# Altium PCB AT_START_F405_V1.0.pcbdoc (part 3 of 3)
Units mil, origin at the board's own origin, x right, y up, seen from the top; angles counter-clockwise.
Board outline 15424.54 x 3535.36 mil, 2 copper layers (Top Layer, Bottom Layer); 147 components, 139 nets, 556 pads, 794 vias.
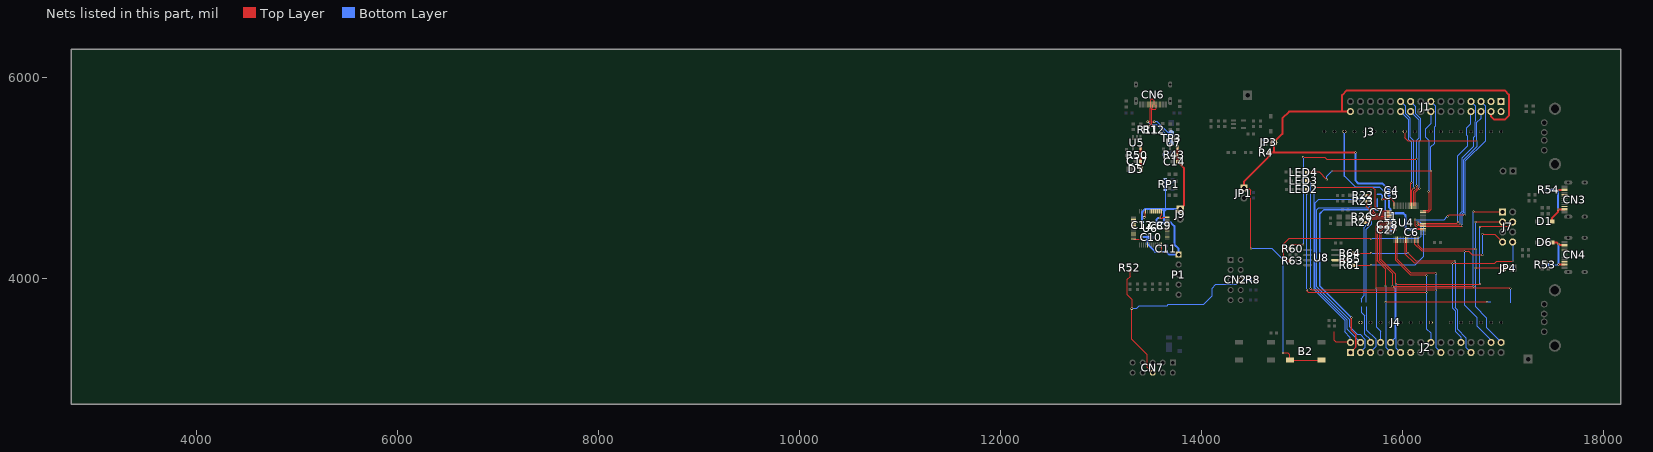
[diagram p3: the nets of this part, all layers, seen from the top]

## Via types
v1: diameter 19.68, hole 11.81, Top Layer to Bottom Layer, 688 vias
v2: diameter 19.69, hole 11.81, Top Layer to Bottom Layer, 42 vias
v3: diameter 19.7, hole 11.81, Top Layer to Bottom Layer, 30 vias
v4: diameter 23.62, hole 11.81, Top Layer to Bottom Layer, 17 vias
v5: diameter 27.56, hole 13.78, Top Layer to Bottom Layer, 15 vias
v6: diameter 27.56, hole 15.75, Top Layer to Bottom Layer, 2 vias

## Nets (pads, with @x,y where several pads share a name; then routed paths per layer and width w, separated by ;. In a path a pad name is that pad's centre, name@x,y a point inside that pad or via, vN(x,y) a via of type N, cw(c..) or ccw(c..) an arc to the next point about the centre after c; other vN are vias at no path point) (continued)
PB12: J2.30 J7.7 U4.30 | length 2216.6
  Top Layer w6: U4.30@16124.19,4389.27 16124.19,4346.32 16196.95,4273.56 v1(16617.58,4273.56) 16660.31,4273.56 16694.67,4239.21 v1(16799.22,4239.21) ; v1(16799.22,4444.56) 16920.47,4444.56 J7.7@16998.88,4366.16
  Bottom Layer w6: v1(16617.58,4273.56) 16617.58,3742.57 16740.58,3619.57 16740.58,3532.57 J2.30@16883.87,3389.28 ; v1(16799.22,4239.21) v1(16799.22,4444.56) ; J2.30@16883.88,3367.14 J2.30@16883.88,3389.26
PB13: J2.32 J7.3 JP4.2 U4.32 | length 2488.6
  Top Layer w6: U4.32@16155.68,4389.27 16155.68,4339.45 16199.17,4295.97 v1(16730.17,4295.97) ; v1(16730.17,4107.65) 16730.27,4107.56 JP4.2@17003.58,4107.56 ; v1(16730.17,4566.16) J7.3@16998.88,4566.16
  Bottom Layer w6: v1(16730.17,4566.16) v1(16730.17,4295.97) v1(16730.17,4107.65) 16730.17,3719.97 16841.58,3608.57 16841.58,3512.57 16983.88,3370.26 J2.32@16983.88,3367.14
PC0: J2.8 U4.8 | length 2802.9
  Top Layer w6: U4.8@15868.28,4566.44 15779.45,4566.44 15739.58,4526.56 v1(15739.58,3906.2) 17075.94,3906.2 v1(17076.58,3905.57)
  Bottom Layer w6: v1(15739.58,3906.2) 15739.58,3521.95 15783.88,3477.65 J2.8@15783.88,3367.14 ; 17076.58,3762.97 v1(17076.58,3905.57)
PC1: J2.9 U4.9 | length 2479.8
  Top Layer w6: v1(15834.61,3767.57) v2(16842.58,3767.57) ; v1(15834.58,3927.57) 15834.58,4095.57 15752.58,4177.56 15752.58,4510.56 15792.7,4550.69 U4.9@15868.28,4550.69
  Bottom Layer w6: v1(15834.58,3927.57) v1(15834.61,3767.57) 15834.58,3316.45 J2.9@15883.88,3267.14 ; v2(16842.58,3767.57) 16880.08,3767.57 ; 16878.83,3768.82 16880.08,3767.57 ; 16881.83,3765.82 16880.08,3767.57
PC2: J2.10 J7.1 U4.10 | length 3166.8
  Top Layer w6: U4.10@15868.28,4534.94 15805.96,4534.95 15768.58,4497.56 15768.58,4186.56 15903.58,4051.57 v1(15903.58,3926.57) 16705.58,3926.57 v1(16706.58,3925.57) ; v1(16706.58,4668.56) 16996.47,4668.56 J7.1@16998.88,4666.16
  Bottom Layer w6: J2.10@15883.88,3367.14 15924.58,3407.84 15924.58,3905.57 v1(15903.58,3926.57) ; v1(16706.58,3925.57) v1(16706.58,4668.56)
PC3: J2.11 J7.4 U4.11 | length 3150.1
  Top Layer w6: U4.11@15868.28,4519.19 15825.2,4519.19 15784.58,4478.56 15784.58,4196.03 15936.58,4044.03 v1(15936.58,3946.79) ; v1@15934.58,3948.79 v1(15936.58,3946.79) ; v1(16772.28,4516.56) 17049.28,4516.56 J7.4@17098.88,4566.16 ; v1(16772.58,3947.57) 16771.58,3946.57 15936.8,3946.57 v1(15936.58,3946.79)
  Bottom Layer w6: v1(15936.58,3946.79) 15936.58,3314.45 J2.11@15983.88,3267.14 ; v1(16772.28,4516.56) 16772.28,3947.86 v1(16772.58,3947.57)
PC4: J2.24 J7.8 U4.24 | length 2272.7
  Top Layer w6: U4.24@16029.7,4389.27 16029.7,4245.81 16121.95,4153.56 v2(16498.58,4153.56) 16918.58,4153.56 16941.58,4176.56 v1(17099.58,4176.56)
  Bottom Layer w6: v2(16498.58,4153.56) 16498.58,3712.57 16526.58,3684.57 16526.58,3479.03 16583.88,3421.74 J2.24@16583.88,3367.14 ; J7.8@17098.88,4366.16 17099.58,4365.47 v1(17099.58,4176.56)
PC5: J2.25 R64.1 U4.25 | length 2156.1
  Top Layer w6: R64.1@15513.84,4255 v3(15690.52,4255) ; U4.25@16045.45,4389.27 16045.45,4267.06 v3(16057.52,4255) 16139.95,4172.56 v2(16525.58,4172.56)
  Bottom Layer w6: v3(15690.52,4255) v3(16057.52,4255) ; v2(16525.58,4172.56) 16525.58,3713.43 16544.58,3694.43 16544.58,3502.7 16632.58,3414.7 16632.58,3318.43 J2.25@16683.88,3267.14
PC6: J1.5 U4.37 | length 1899.3
  Top Layer w6: v1(16125.52,4589) 16125.52,4532 16154.07,4503.44 U4.37@16206.86,4503.44 ; v1(16448.58,4620.56) 16461.58,4633.56 v1(16619.58,4633.56)
  Bottom Layer w6: v1(16125.52,4589) 16417.01,4589 v1(16448.58,4620.56) ; v1(16619.58,4633.56) 16626.58,4640.56 16626.58,5173.56 16828.58,5375.56 16828.58,5719.73 J1.5@16783.44,5764.86
PC7: J1.6 J3.2 U4.38 | length 2399.2
  Top Layer w6: J3.2@16023.88,5465.56 16023.88,5406.49 16060.81,5369.56 v2(16742.58,5369.56) ; U4.38@16206.86,4519.19 16585.21,4519.2 v1(16596.42,4530.41)
  Bottom Layer w6: v1(16596.42,4530.41) 16596.42,4646.11 16611.58,4661.26 16611.58,5184.56 16742.58,5315.56 v2(16742.58,5369.56) 16742.58,5558.56 16783.44,5599.44 J1.6@16783.44,5664.86
PC8: J1.7 R63.1 U4.39 | length 3486.1
  Top Layer w6: R63.1@14882.2,4180 14854.52,4180 14816.52,4218 14816.52,4346 14867.52,4397 v3(15690.52,4397) ; v3(16149.52,4539) 16153.57,4534.94 U4.39@16206.86,4534.94 16561.96,4534.95 v1(16575.22,4548.21)
  Bottom Layer w6: v3(15690.52,4397) 16160.52,4397 16184.52,4421 16184.52,4518 16163.52,4539 v3(16149.52,4539) ; v1(16575.22,4548.21) 16575.22,4651.57 16597.58,4673.92 16597.58,5206.56 16708.87,5317.85 16708.87,5407.23 16726.58,5424.94 16726.58,5565.56 16733.58,5572.56 16733.58,5716.56 16685.28,5764.86 J1.7@16683.44,5764.86
PC9: J1.8 R61.1 U4.40 | length 2695.6
  Top Layer w6: R61.1@15513.84,4136 v3(15687.52,4136) ; v3(16149.52,4567) 16165.83,4550.69 U4.40@16206.86,4550.69 16538.7,4550.69 v2(16553.58,4565.56)
  Bottom Layer w6: v3(15687.52,4136) 16125.52,4136 16208.52,4219 16208.52,4532 16173.52,4567 v3(16149.52,4567) ; v2(16553.58,4565.56) 16553.58,5224.56 16652.58,5323.56 16652.58,5417.56 16640.58,5429.56 16640.58,5502.56 16683.44,5545.44 J1.8@16683.44,5664.86
PC10: J1.19 U4.51 | length 1103.9
  Top Layer w6: U4.51@16124.19,4727.85 16124.19,4855.18 v2(16170.58,4901.56)
  Bottom Layer w6: J1.19@16083.44,5764.86 16134.58,5713.73 16134.58,5641.56 16184.58,5591.56 16184.58,5385.56 16170.58,5371.56 v2(16170.58,4901.56)
PC11: J1.20 R60.1 U4.52 | length 3170.3
  Top Layer w6: R60.1@14882.2,4299 14882.2,4327.18 14895.49,4340.47 v3(15013.05,4340.47) ; v3(15013.52,5211) 15227.52,5211 15247.56,5190.96 v3(16142.58,5190.96) ; U4.52@16108.44,4727.85 16108.44,4864.44 16142.58,4898.56 v2(16142.58,4929.56)
  Bottom Layer w6: v3(15013.05,4340.47) v3@15013.52,4340.94 ; v3@15013.52,4340.47 v3@15013.52,4340.94 ; v3(15013.52,5211) v3@15013.52,4340.94 ; J1.20@16083.44,5664.86 16168.58,5579.73 16168.58,5403.56 16142.58,5377.56 v3(16142.58,5190.96) v2(16142.58,4929.56)
PC12: J1.21 U4.53 | length 1100.4
  Top Layer w6: U4.53@16092.69,4727.85 16092.69,4883.68 v2(16114.58,4905.56)
  Bottom Layer w6: J1.21@15983.44,5764.86 16032.58,5715.73 16032.58,5643.56 16078.58,5597.56 16078.58,5411.56 16114.58,5375.56 v2(16114.58,4905.56)
PC13: J2.2 U4.2 | length 2911.7
  Top Layer w6: v1(15116.58,4911.56) 15702.58,4911.56 15728.58,4885.56 15728.58,4718.56 15786.22,4660.93 U4.2@15868.28,4660.93 ; 15317.85,3473.57 15322.76,3473.57 15320.58,3471.38 15320.58,3390.57 15344,3367.14 J2.2@15483.88,3367.14
  Bottom Layer w6: v1(15116.58,4911.56) 15116.58,3895.57 15425.58,3586.57 15425.58,3471.57 15483.88,3413.27 J2.2@15483.88,3367.14
PC14: J2.3 | length 2278.3
  Bottom Layer w6: J2.3@15583.88,3267.14 15633.58,3316.84 15633.58,3395.57 15586.58,3442.57 15554.58,3442.57 15475.58,3521.57 15475.58,3592.57 15147.58,3920.57 15147.58,4687.56 15169.58,4709.56 15659.58,4709.56 15689.58,4739.56 15689.58,4793.28
PC14/LEXT_IN: R22.1 U4.3 | length 480.3
  Top Layer w6: R22.1@15637.08,4831.56 15688.55,4831.56 ; v1(15688.58,4880.56) 15688.58,4695.56 15738.96,4645.18 U4.3@15868.28,4645.18
  Bottom Layer w6: v1(15688.58,4880.56) 15689.58,4879.56 15689.58,4837.69
PC15: J2.4 | length 2051.5
  Bottom Layer w6: J2.4@15583.58,3367.57 15450.58,3500.57 15450.58,3589.57 15132.58,3907.57 15132.58,4755.68 15170.18,4793.28 15593.58,4793.28
PC15/LEXT_OUT: R23.1 U4.4 | length 448.6
  Top Layer w6: R23.1@15639.08,4773.56 v1(15639.08,4738.92) 15639.08,4721.06 15730.71,4629.43 U4.4@15868.28,4629.43
  Bottom Layer w6: 15605.58,4837.69 15605.69,4837.56 15633.58,4837.56 15639.08,4832.06 v1(15639.08,4738.92)
PD2: J1.22 U4.54 | length 988.3
  Top Layer w6: U4.54@16076.94,4727.85 16076.94,4941.93 v2(16092.58,4957.56)
  Bottom Layer w6: J1.22@15983.58,5664.56 16064.58,5583.56 16064.58,5386.45 16092.58,5358.45 v2(16092.58,4957.56)
PF0: J2.5 | length 511.8
  Bottom Layer w6: 15643.58,3720.28 15642.58,3719.28 15642.58,3494.57 15733.58,3403.57 15733.58,3322.57 15683.88,3272.86 J2.5@15683.88,3267.14
PF0/HEXT_IN: R26.1 U4.5 | length 1122.1
  Top Layer w6: R26.1@15628.08,4615.56 15629.17,4614.47 v1(15671.97,4614.33) U4.5@15868.28,4613.69
  Bottom Layer w6: 15643.58,3764.68 15643.58,4495.06 15695.52,4547 15695.52,4591.62 15672.81,4614.33 v1(15671.97,4614.33)
PF1: J2.6 | length 393.2
  Bottom Layer w6: 15589.58,3721.28 15589.58,3669.57 15628.58,3630.57 15628.58,3446.57 15683.88,3391.26 J2.6@15683.88,3367.14
PF1/HEXT_OUT: R27.1 U4.6 | length 1084.7
  Top Layer w6: R27.1@15628.08,4561.56 v1(15670.58,4561.56) 15706.94,4597.94 U4.6@15868.28,4597.94
  Bottom Layer w6: 15589.58,3765.68 15589.58,3802.06 15622.52,3835 15622.52,4513.51 v1(15670.58,4561.56)
PF4: J2.18 LED2.2 U4.18 | length 3464.8
  Top Layer w6: v1(15049.23,3890.48) 15049.23,3880.04 15064.35,3864.91 v1(16240.58,3864.91) ; v1(15049.23,4848.22) 15049.53,4848.52 LED2.2@15049.53,4889.77 ; U4.18@15935.22,4389.27 15935.22,4184.93 16085.58,4034.57 v2(16240.58,4034.57)
  Bottom Layer w6: v1(15049.23,3890.48) v1(15049.23,4848.22) ; v2(16240.58,4034.57) v1(16240.58,3864.91) 16240.58,3505.57 16283.88,3462.28 J2.18@16283.88,3367.14
PF5: J2.19 LED3.2 U4.19 | length 3807.3
  Top Layer w6: LED3.2@15049.53,4975.77 v1(15085.37,4975.77) ; v1(15085.37,3903.35) 15102.48,3886.25 v1(16333.58,3886.25) ; U4.19@15950.97,4389.27 15950.97,4194.18 16090.58,4054.57 v2(16333.58,4054.57)
  Bottom Layer w6: v1(15085.37,3903.35) v1(15085.37,4975.77) ; v2(16333.58,4054.57) v1(16333.58,3886.25) 16333.58,3317.43 J2.19@16383.88,3267.14
PF6: J1.15 LED4.2 U4.47 | length 2526.9
  Top Layer w6: LED4.2@15049.53,5059.77 15175.75,5059.77 v3(15248.52,4987) ; v1(15302.58,5073.56) v2(16284.58,5073.56) 16284.58,4686.56 16258.93,4660.93 U4.47@16206.86,4660.93
  Bottom Layer w6: v3(15248.52,4987) 15248.52,5019.51 v1(15302.58,5073.56) ; J1.15@16283.44,5764.86 16332.58,5715.73 16332.58,5521.56 16322.58,5511.56 16322.58,5351.56 16284.58,5313.56 v2(16284.58,5073.56)
PF7: J1.16 U4.48 | length 1073.3
  Top Layer w6: U4.48@16206.86,4676.68 16252.69,4676.68 16261.58,4685.56 v2(16261.58,4869.56)
  Bottom Layer w6: v2(16261.58,4869.56) 16262.58,4870.56 16262.58,5381.56 16230.58,5413.56 16230.58,5489.56 16283.44,5542.44 J1.16@16283.44,5664.86
SCK: R65.2 U8.6 | length 123.1
  Top Layer w6: U8.6@15334.98,4187 15446.02,4187 R65.2@15454.52,4195.5
SWO: CN2.6 CN7.6 R8.2 R52.1 | length 2484.5
  Top Layer w6: R52.1@13290.15,4080.97 13290.15,4023.01 13256.58,3989.45 13256.58,3845.57 13306.58,3795.57 v4(13306.58,3703.57) 13306.58,3398.57 13462.58,3242.57 13462.58,3118.78 CN7.6@13515.34,3066.01
  Bottom Layer w6: v4(13306.58,3703.57) 13350.58,3703.57 13374.58,3727.57 13653.58,3727.57 13665.58,3739.57 14016.58,3739.57 14101.58,3824.57 14101.58,3903.57 14139.58,3941.57 14343.65,3941.57 CN2.6@14390.92,3988.84 ; CN2.6@14390.97,3988.89 R8.2@14490.58,3988.89
USB+: CN6.A6 CN6.B6 R11.1 TP3.3 | length 723.2
  Top Layer w11.2: v5(13466.68,5562.67) 13490.33,5562.67 ; R11.1@13469.58,5514.56 13490.33,5535.31 13490.33,5562.67 ; CN6.A6@13528.38,5734.27 13528.38,5773.77 13516.58,5785.56 13499.58,5785.56 13489.58,5775.56 13489.58,5734.77 CN6.B6@13489.08,5734.27 13489.08,5698.11 13490.33,5696.86 13490.33,5562.67
  Bottom Layer w11.2: v5(13466.68,5562.67) 13497.78,5531.56 13553.58,5531.56 13699.92,5385.22 TP3.3@13699.92,5350.02
USB-: CN6.A7 CN6.B7 R12.1 TP3.2 | length 554.9
  Top Layer w11.2: CN6.A7@13508.77,5734.27 13508.77,5698.11 13507.52,5696.86 13507.52,5682.94 ; R12.1@13528.58,5514.23 13507.52,5535.27 13507.52,5562.67 ; v5(13531.68,5562.67) 13507.52,5562.67 ; CN6.B7@13548.08,5734.27 13548.08,5692.06 13539.58,5683.56 13508.15,5683.56 13507.52,5682.94 ; 13507.52,5562.67 13507.52,5682.94
  Bottom Layer w11.2: v5(13531.68,5562.67) 13561.47,5562.67 13674.12,5450.02 TP3.2@13699.92,5450.02
VBUS_FS: CN3.A4B9 CN3.B4A9 D1.1 R54.2 | length 531.4
  Top Layer w20: D1.1@17492.58,4572.56 17492.58,4607.28 17549.08,4663.78 v1(17549.08,4692.06) CN3.A4B9@17615.28,4692.06 ; v1(17549.08,4884.06) 17550.08,4885.06 CN3.B4A9@17615.28,4885.06
  Bottom Layer w6: R54.2@17485.58,4884.56 v1@17548.58,4884.56
  Bottom Layer w20: v1@17548.58,4884.56 v1(17549.08,4884.06) v1(17549.08,4692.06)
VBUS_HS: CN4.A4B9 CN4.B4A9 D6.1 R53.2 | length 520.2
  Top Layer w20: D6.1@17474.58,4363.56 17537.58,4363.56 v1(17554.53,4346.61) 17566.08,4335.06 CN4.B4A9@17615.28,4335.06 ; v1(17554.57,4142.06) CN4.A4B9@17615.28,4142.06
  Bottom Layer w6: R53.2@17452.24,4141.56 17554.07,4141.56 v1(17554.57,4142.06)
  Bottom Layer w20: v1(17554.57,4142.06) v1@17554.57,4346.56
VCC: C8.1 C9.1 C10.1 C11.1 C12.1 C14.1 J9.1 P1.1 R43.2 RP1.1 RP1.2 RP1.3 RP1.4 U6.1 U6.9 U6.24 U6.36 U6.48 U7.5 | length 3073.1
  Top Layer w10: U6.24@13324.5,4396.43 13390.33,4396.43 v4(13407.92,4414.02) ; v4(13430.58,4611.56) 13442.6,4623.6 U6.9@13442.6,4672.02 ; U6.36@13600.08,4337.36 13600.08,4269.27 v4(13600.34,4269.02) ; U6.1@13600.08,4672.02 13600.08,4631.76 13583.34,4615.02 v4(13583.34,4605.02) 13612.34,4605.02 13620.3,4612.97 U6.48@13659.15,4612.97
  Top Layer w20: C14.1@13764.14,5164.56 13827.58,5101.12 13827.58,4731.16 J9.1@13789.38,4692.97 ; C14.1@13764.34,5165.3 U7.5@13764.34,5306.9
  Bottom Layer w10: 13638.82,4682.98 13640.58,4684.73 13640.58,4693.02 RP1.1@13640.58,4886.56 RP1.2@13640.58,4921.99 RP1.3@13640.58,4957.44 RP1.4@13640.58,4992.86
  Bottom Layer w20: C12.1@13407.34,4559.02 13407.34,4663.02 13437.34,4693.02 13610.53,4693.02 ; 13407.35,4613.02 13429.12,4613.02 v4(13430.58,4611.56) ; v4(13407.92,4414.02) 13465.34,4414.02 13465.34,4344.02 13540.34,4269.02 v4(13600.34,4269.02) 13650.58,4272.06 13681.08,4241.56 P1.1@13772.58,4241.56 13772.58,4299.56 13730.34,4341.8 13730.34,4525.02 13696.34,4559.02 C9.1@13628.34,4559.02 ; v4(13583.34,4605.02) 13567.34,4605.02 13554.34,4592.02 13554.34,4559.02 C9.1@13628.34,4559.02 ; J9.1@13789.34,4693.02 13649.06,4693.02 ; 13610.53,4693.02 13610.53,4690.52 13628.34,4672.7 ; 13610.53,4693.02 13640.58,4693.02 13649.06,4693.02 ; C9.1@13628.34,4559.02 13628.34,4672.7 ; 13628.34,4672.7 13638.82,4682.98 13649.06,4693.02
VCC3.5V: C17.1 D5.2 R50.2 U5.5 | length 488.1
  Top Layer w20: U5.5@13395.58,5304.56 13395.15,5109.74 D5.2@13396.33,5108.56
  Top Layer w25: D5.2@13389.33,5098.56 D5.2@13395.14,5104.38 ; U5.5@13395.14,5304.9 C17.1@13395.14,5172.56 ; D5.2@13397.33,5090.56 13395.14,5092.76 D5.2@13395.14,5104.38 ; D5.2@13395.15,5104.39 13395.15,5109.74 C17.1@13395.14,5172.56 ; D5.2@13395.14,5104.38 C17.1@13395.14,5172.56
VDD: B2.1 B2.2 C4.1 C5.1 C6.1 C7.1 J1.4 J1.32 J2.1 JP1.1 JP3.2 L1.1 R4.1 U4.1 U4.36 U4.64 | length 11119
  Top Layer w6: JP1.1@14423.58,4903.56 14472.95,4903.56 14493.52,4883 v3(14493.52,4301)
  Top Layer w8: v1(15792.58,4689.56) 15805.47,4676.68 U4.1@15868.28,4676.68 ; v1(15869.11,4791.31) 15869.37,4791.56 15892.58,4791.56 15919.47,4764.68 U4.64@15919.47,4727.85 ; v1@16136.58,4487.56 v1(16136.7,4487.69) U4.36@16206.86,4487.69
  Top Layer w10: v1(14813.58,3261.57) 14862.58,3261.57 14881.09,3243.05 B2.2@14881.09,3191.99 B2.1@15196.06,3191.99
  Top Layer w15: J2.1@15483.88,3267.14 15534.58,3317.84 15534.58,3445.57 15493.58,3486.57 v1(15493.58,3613.57) ; v1@15799.58,4791.56 v1(15799.83,4791.31) v1(15869.11,4791.31)
  Top Layer w20: JP1.1@14423.58,4903.56 14423.58,4968.45 14675.08,5219.95 R4.1@14675.08,5257.56 14720.43,5257.56 14720.58,5257.71 ; J1.32@15483.44,5664.86 15400.98,5664.86 ; v1(15532.72,5257.71) 14720.58,5257.71 ; J1.4@16883.44,5664.86 16883.44,5614.69 16910.58,5587.56 17024.58,5587.56 17061.58,5624.56 17061.58,5834.56 17020.58,5875.56 15446.58,5875.56 15400.58,5829.56 15400.58,5665.27 15400.98,5664.86 ; 14720.58,5257.71 JP3.2@14720.58,5357.57 14806.58,5443.56 14806.58,5597.56 14873.88,5664.86 15400.98,5664.86
  Bottom Layer w10: v3(14493.52,4301) 14704.52,4301 14813.58,4191.94 v1(14813.58,3261.57)
  Bottom Layer w15: v1(15493.58,3613.57) 15177.58,3929.57 15177.58,4646.84 15216.3,4685.56 15746.08,4685.56 C7.1@15750.58,4690.06 ; 15750.58,4795.28 C7.1@15750.58,4690.06 ; 15750.58,4839.69 15790.45,4839.69 15799.83,4830.31 v1(15799.83,4791.31) ; v1(15792.58,4689.56) 15751.08,4689.56 C7.1@15750.58,4690.06
  Bottom Layer w20: v1(15532.72,5257.71) 15532.72,4979.88 15564.04,4948.56 15804.08,4948.56 C4.1@15869.08,4883.56 v1(15869.11,4791.31) ; 15869.08,4808.56 v1(15869.11,4791.31) ; v1(16136.7,4487.69) 16135.33,4489.06 C6.1@16091.58,4489.06 16053.45,4489.06 16031.52,4511 16031.52,4632.88 16011.52,4652.88 L1.1@15884.58,4652.88 15883.58,4653.88 15883.58,4693.56 15869.11,4708.03 v1(15869.11,4791.31)
VDDA: C27.2 C28.2 J3.8 L1.2 U4.13 | length 1446
  Top Layer w9: U4.13@15868.28,4487.69 15868.41,4487.56 v2(15933.58,4487.56)
  Bottom Layer w15: J3.8@15423.88,5465.56 15423.88,5022.91 15533.22,4913.56 15773.58,4913.56 15832.58,4854.56 15832.58,4606.56 15846.9,4592.24 L1.2@15884.58,4592.24 C28.2@15884.58,4536.56 ; C27.2@15884.58,4487.56 v2(15933.58,4487.56)
  Bottom Layer w20: C27.2@15884.58,4487.56 C28.2@15884.58,4536.56
"": CN3.A8 CN3.B8 CN4.A8 CN4.B8 CN6.A8 CN6.B8 J1.1 J1.2 J1.3 J2.13 J4.1 J4.8 U6.2 U6.3 U6.4 U6.5 U6.6 U6.14 U6.15 U6.16 U6.17 U6.18 U6.21 U6.22 U6.29 U6.38 U6.41 U6.42 U6.43 U6.45 U6.46

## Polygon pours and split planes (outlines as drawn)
GND on Top Layer (solid, remove dead copper, pour order 0): 17151.58,5986.56 17151.58,5680.4 17151.54,5680.37 17381.77,5680.37 17455.58,5606.56 17455.58,4937.56 17456.58,4936.56 17699.53,4936.56 17699.83,4936.27 17699.83,4645.82 17699.58,4645.56 17596.16,4645.56 17595.58,4646.15 17595.58,4386.27 17696.88,4386.27 17700.58,4382.56 17700.58,4095.57 17604.58,4095.57 17604.58,3968.57 17455.58,3968.57 17455.58,3042.57 17456.58,3041.57 13182.58,3041.57 13182.58,5726.56 13181.58,5727.56 13368.58,5727.56 13368.58,5792.28 13348.48,5812.38 13662.39,5812.38 13662.58,5812.56 13662.58,5731.56 13940.58,5731.56 13940.58,5984.56 13942.58,5986.56
GND on Bottom Layer (solid, remove dead copper, pour order 1): 17151.58,5986.56 17151.58,5680.4 17382.74,5680.4 17455.58,5607.56 17455.58,4937.56 17596.53,4937.56 17602.58,4200.56 17604.57,4094.86 17603.58,3968.57 17455.58,3968.57 17455.58,3040.64 13183.5,3040.64 13182.58,3041.57 13182.58,5727.56 13368.58,5727.56 13368.58,5807.56 13373.58,5812.56 13662.58,5812.56 13662.58,5731.56 13939.58,5731.56 13939.58,5983.56 13942.98,5986.97 17151.17,5986.97

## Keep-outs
Top Layer:
  region net "": 13642.58,4449.56 13675.58,4449.56 13675.58,4442.56 13642.58,4442.56
Board Outline Layer:
  lines w8 net "": 13799.95,3000.67 ccw(c13802.87,3079.36) 13881.61,3079.36 13881.87,3518.01 13921.13,3518.01 13921.13,3079.36 ccw(c13999.87,3079.36) 13999.87,3000.62 ; 13802.87,6029.91 cw(c13802.87,5951.17) 13881.61,5951.17 13881.61,5631.02 13921.13,5631.02 13921.13,5950.91 cw(c13999.87,5950.91) 13999.87,6029.65 ; 13920.13,4825.02 13881.87,4825.02 13881.87,3809.02 ; 13920.87,4824.28 13920.87,3809.01 13881.87,3809.01 ; 13999.24,3000.05 ccw(c13999.87,3004.02) 13999.87,3000 ; 13999.87,6030.43 ccw(c13999.9,6034.44) 13999.9,6030.43 ; 17836.3,6030.43 cw(c17836.87,6026.45) 17836.87,6030.47 ; 13881.87,3809.02 13881.87,3809.01 ; 13881.87,3606.01 13881.87,3698.01 13921.13,3698.01 13921.13,3606.01 13881.87,3606.01 ; 13881.87,4903.02 13881.87,5553.02 13921.13,5553.02 13921.13,4903.27 13920.87,4903.02 13881.87,4903.02
  lines w10 net "": 13149.49,5947.67 cw(c13153.5,5947.67) 13150.15,5949.89 cw(c13232.87,5947.41) 13231.42,6030.16 cw(c13232.87,6026.41) 13232.87,6030.43 ; 13149.49,5947.67 13149.49,5947.67 ; 13149.49,5947.67 13149.9,3082.97 ; 13149.9,3082.97 13149.9,3082.97 ; 13149.9,3082.97 ccw(c13153.92,3082.97) 13150.17,3081.52 ccw(c13232.92,3082.97) 13231.59,3000.23 ccw(c13232.92,3004.02) 13232.92,3000 ; 13232.87,6030.43 13999.81,6030.43 13999.87,6030.43 17281.13,6030.43 17836.3,6030.43 17836.87,6030.47 cw(c17836.87,5947.71) 17919.61,5949.17 cw(c17915.87,5947.71) 17919.89,5947.71 ; 13232.87,6030.43 13232.87,6030.43 ; 13232.92,3000 13232.92,3000 ; 13232.92,3000 13998.61,3000 ; 13998.61,3000 13998.61,3000 ; 13998.61,3000 ccw(c13998.61,3004.02) 13999.24,3000.05 13999.87,3000 17281.13,3000 17836.87,3000 ; 17836.87,3000 17836.87,3000 ; 17836.87,3000 ccw(c17836.87,3082.76) 17919.61,3081.3 ccw(c17915.87,3082.76) 17919.88,3082.76 ; 17919.88,3082.76 17919.88,3082.76 ; 17919.88,3082.76 17919.88,5947.72 ; 17919.88,5947.72 17919.89,5947.71

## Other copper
Top Layer:
  drawing of 526 lines, arcs and shapes, not listed
Bottom Layer:
  drawing of 410 lines, arcs and shapes, not listed

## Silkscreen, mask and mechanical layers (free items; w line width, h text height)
Top Silkscreen Layer:
  circle w50 net "": c17073.58,5764.56 r1
  circle w50 net "": c15389.58,3267.57 r1
  lines w5 net "": 16867.58,5337.56 16869.58,5337.56 ; 17005.58,5354.56 17003.58,5354.56 ; 16869.58,5337.56 16888.58,5356.56 16888.58,5361.56 ; 16869.58,5337.56 16905.58,5337.56 ; 16869.58,5337.56 16871.58,5337.56 16888.58,5354.56 ; 16888.58,5337.56 16885.58,5340.56 16874.58,5340.56 16875.58,5339.56 16880.58,5339.56 16887.08,5346.06 16888.58,5346.06 16897.08,5337.56 16905.58,5337.56 ; 16888.58,5337.56 16888.58,5354.56 ; 16888.58,5337.56 16893.58,5342.56 ; 16888.58,5354.56 16893.58,5349.56 16893.58,5342.56 ; 16888.58,5354.56 16908.58,5334.56 ; 16888.58,5354.56 16888.58,5361.56 ; 16888.58,5361.56 16886.58,5361.56 16859.58,5334.56 16908.58,5334.56 ; 16888.58,5361.56 16915.58,5334.56 16908.58,5334.56 ; 16893.58,5342.56 16900.58,5342.56 16905.58,5337.56 ; 16905.58,5337.56 16908.58,5334.56 ; 16964.58,5357.56 17013.58,5357.56 16986.58,5330.56 16984.58,5330.56 ; 16964.58,5357.56 16957.58,5357.56 16984.58,5330.56 ; 16964.58,5357.56 16967.58,5354.56 ; 16964.58,5357.56 16984.58,5337.56 ; 16967.58,5354.56 16976.08,5354.56 16984.58,5346.06 16986.08,5346.06 16992.58,5352.56 16997.58,5352.56 16998.58,5351.56 16987.58,5351.56 16984.58,5354.56 ; 16967.58,5354.56 16972.58,5349.56 16979.58,5349.56 ; 16967.58,5354.56 17003.58,5354.56 ; 16979.58,5349.56 16984.58,5354.56 ; 16979.58,5349.56 16979.58,5342.56 16984.58,5337.56 ; 16984.58,5330.56 16984.58,5337.56 ; 16984.58,5330.56 16984.58,5335.56 17003.58,5354.56 ; 16984.58,5337.56 16984.58,5354.56 ; 16984.58,5337.56 17001.58,5354.56 17003.58,5354.56
  lines w6 net "": 13364.57,3292.28 13364.57,3591.28 ; 13464.57,3293.28 13464.57,3592.28 ; 13564.57,3293.28 13564.57,3593.28 ; 13666.57,3292.28 13666.57,3586.28
  lines w8 net "": 13462.92,3218.01 13462.92,3258.01 13562.92,3258.01 13562.92,3217.01 ; 13753.47,3272.01 13716.47,3235.01 13677.47,3274.01 13753.47,3274.01 ; 14177.57,4226.19 14177.57,4150.19 14216.57,4189.19 14179.57,4226.19 ; 14240.57,3939.2 14200.57,3939.2 14200.57,4039.2 14241.57,4039.2
  lines w10 net "": 15596.17,5192.72 17011.87,5192.72 ; 15870.08,3853.57 16323.08,3853.57 ; 16458.58,3853.57 17018.58,3853.57
  text "43" at 16450.01,5949.73 h38.28
  text "33" at 16956.01,5949.73 h38.28
  text "53" at 15956.01,5947.73 h38.28
  text "63" at 15450.01,5945.73 h38.28
  text "F6" at 16277.73,5838.29 h34.45 r45
  text "A8" at 16574.84,5836.58 h34.45 r45
  text "C8" at 16672.84,5836.58 h34.45 r45
  text "C12" at 15974.55,5836.29 h34.45 r45
  text "A12*" at 16367.51,5835.98 h34.45 r45
  text "A10" at 16466.55,5836.29 h34.45 r45
  text "B7" at 15684.84,5834.58 h34.45 r45
  text "NC" at 16873.62,5835.36 h34.45 r45
  text "B5" at 15780.52,5834.26 h34.45 r45
  text "B3" at 15876.78,5834.28 h34.45 r45
  text "B8" at 15578.84,5832.58 h34.45 r45
  text "C6" at 16778.84,5832.58 h34.45 r45
  text "NC" at 16979.62,5833.36 h34.45 r45
  text "C10" at 16068.55,5832.29 h34.45 r45
  text "A14" at 16162.55,5832.29 h34.45 r45
  text "GND" at 15467.07,5825.52 h34.45 r45
  text "GND" at 14557.65,5809.28 h45.94
  text "B9" at 15572.84,5538.58 h34.45 r45
  text "F11" at 15661.9,5535.78 h28.71 r45
  text "F7" at 16271.74,5534.29 h34.45 r45
  text "D2" at 15977.46,5533.13 h34.45 r45
  text "C9" at 16674.84,5532.58 h34.45 r45
  text "C11" at 16069.87,5532.27 h34.45 r45
  text "A9" at 16574.84,5530.58 h34.45 r45
  text "C7" at 16774.84,5530.58 h34.45 r45
  text "B6" at 15774.53,5530.26 h34.45 r45
  text "B4" at 15870.8,5530.28 h34.45 r45
  text "NC" at 16977.62,5525.36 h34.45 r45
  text "A15" at 16168.55,5524.29 h34.45 r45
  text "A13" at 16362.55,5522.29 h34.45 r45
  text "A11*" at 16464.26,5522 h34.45 r45
  text "VDD" at 16864.55,5515.29 h34.45 r45
  text "VDD" at 15446.55,5514.29 h34.45 r45
  text "4" at 16601.8,5361.56 h45.56 r90
  text "7" at 16313.8,5359.56 h45.56 r90
  text "2" at 16803.8,5359.56 h45.56 r90
  text "8" at 16147.8,5358.56 h45.56 r90
  text "13" at 15653.98,5332.59 h45.94 r90
  text "12" at 15747.98,5332.59 h45.94 r90
  text "IDD" at 14793.42,5327.4 h45.94
  text "#3" at 16709.98,5314.89 h45.94 r90
  text "#9" at 16047.98,5312.89 h45.94 r90
  text "#6" at 16405.98,5312.89 h45.94 r90
  text "#5" at 16509.98,5312.89 h45.94 r90
  text "#11" at 15851.98,5304.54 h45.94 r90
  text "#10" at 15947.98,5284.84 h45.94 r90
  text "SCL" at 15245.98,5269.64 h45.94 r90
  text "GND" at 15547.98,5265.24 h45.94 r90
  text "SDA" at 15349.98,5263.04 h45.94 r90
  text "FS_HOST" at 17303.86,5245.57 h45.94 r90
  text "TX 1" at 16906.86,5233.63 h45.94 r90
  text "RX 0" at 17008.86,5230.63 h45.94 r90
  text "DIGITAL(#=PWM)" at 15992.19,5221.83 h40.19
  text "VDDA" at 15445.98,5213.18 h45.94 r90
  text "LD:" at 13803.32,5156 h40.19 r270
  text "AT-Link-EZ V1.4" at 13197.82,5071.38 h57.42 r270
  text "FS_VBUS" at 16604.58,5057.28 h45.94
  text "1" at 13803.99,5054.27 h39.87 r270
  text "2" at 13803.99,4987.27 h39.87 r270
  text "3" at 13803.99,4914.27 h39.87 r270
  text "VDD" at 14220.6,4883.72 h45.95
  text "4" at 13803.99,4839.27 h39.87 r270
  text "BOOT0" at 14122.56,4777.71 h45.94
  text "5V" at 17172.91,4649.31 h40.19
  text "MISO" at 16783.02,4647.83 h40.19
  text "FS_Device" at 17539.86,4599.54 h45.94 r90
  text "SCK" at 16803.5,4542.83 h40.19
  text "MOSI" at 17169.02,4542.83 h40.19
  text "GND" at 17169.5,4447.83 h40.19
  text "RESET" at 16732.53,4442.83 h40.19
  text "NSS" at 16803.5,4342.83 h40.19
  text "PC4" at 17175.78,4337.83 h40.19
  text "AT-Link" at 14161.53,4283.64 h57.42
  text "5V" at 14477.98,4172.83 h40.19
  text "3V3" at 14041.5,4166.83 h40.19
  text "HS_VBUS" at 16604.58,4085.28 h45.94
  text "SWD" at 14045.5,4072.83 h40.19
  text "BOOT0" at 14476.53,4067.83 h40.19
  text "HS_Device" at 17557.86,4038.54 h45.94 r90
  text "SWO" at 14477.5,3967.83 h40.19
  text "SWC" at 14042.5,3957.83 h40.19
  text "AT-START-F405 V1.0" at 15998.65,3909.84 h69.7
  text "USART1_RX" at 14474.6,3862.83 h40.19
  text "NRST" at 14047.02,3857.83 h40.19
  text "POWER" at 16104.53,3789.83 h40.19
  text "ANALOG IN" at 16606.6,3789.83 h40.19
  text "GND" at 14047.5,3767.83 h40.19
  text "USART1_TX" at 14474.6,3762.83 h40.19
  text "AN0" at 16507.28,3640.49 h45.94 r90
  text "AN1" at 16603.28,3640.49 h45.94 r90
  text "AN2" at 16708.28,3639.49 h45.94 r90
  text "AN3" at 16809.28,3639.49 h45.94 r90
  text "AN4" at 16911.28,3639.49 h45.94 r90
  text "AN5" at 17011.28,3639.49 h45.94 r90
  text "IOREF" at 15705.98,3637.23 h45.94 r90
  text "5V" at 16003.98,3636.89 h45.94 r90
  text "RESET" at 15802.98,3636.23 h45.94 r90
  text "3.3V" at 15903.98,3635.78 h45.94 r90
  text "GND" at 16104.98,3636.34 h45.94 r90
  text "GND" at 16204.27,3636.34 h45.94 r90
  text "SWD" at 13594.85,3590.93 h40.19 r270
  text "GND" at 13290.84,3586.64 h40.19 r270
  text "NRST" at 13390.84,3587.12 h40.19 r270
  text "SWC" at 13495.84,3586.64 h40.19 r270
  text "3V3" at 13690.84,3586.64 h40.19 r270
  text "HS_HOST" at 17296.86,3440.57 h45.94 r90
  text "F4" at 16273.74,3438.29 h34.45 r45
  text "B0" at 16656.16,3437.73 h34.45 r45
  text "B2" at 16761.96,3437.71 h34.45 r45
  text "A0" at 16072.16,3436.56 h34.45 r45
  text "A2" at 16165.99,3436.56 h34.45 r45
  text "A4" at 16364.11,3436.56 h34.45 r45
  text "A6" at 16457.93,3436.56 h34.45 r45
  text "F1*" at 15684.55,3436.29 h34.45 r45
  text "C0" at 15776.53,3434.26 h34.45 r45
  text "C2" at 15872.8,3434.28 h34.45 r45
  text "C4" at 16554.17,3434.26 h34.45 r45
  text "B12" at 16862.16,3431.62 h34.45 r45
  text "B13" at 16972.16,3426.82 h34.45 r45
  text "C13" at 15463.09,3425.52 h34.45 r45
  text "BOOT0" at 13599.28,3422.1 h30.14 r270
  text "C15*" at 15570.26,3422 h34.45 r45
  text "SWO" at 13496.83,3421.35 h40.19 r270
  text "GND" at 15968.16,3420.82 h34.45 r45
  text "RX" at 13289.83,3397.87 h40.19 r270
  text "TX" at 13390.84,3396.57 h40.19 r270
  text "5V" at 13689.83,3396.57 h40.19 r270
  text "GND" at 17340.65,3178.28 h45.94
  text "C1" at 15880.84,3142.58 h34.45 r45
  text "A1" at 16176.16,3141.07 h34.45 r45
  text "NC" at 16076.84,3136.58 h34.45 r45
  text "F5" at 16368.84,3136.58 h34.45 r45
  text "B1" at 16776.84,3136.58 h34.45 r45
  text "C3" at 15974.84,3134.58 h34.45 r45
  text "C5" at 16666.84,3132.58 h34.45 r45
  text "A3" at 16260.75,3131.8 h34.45 r45
  text "A7" at 16568.84,3130.58 h34.45 r45
  text "F0*" at 15664.55,3128.29 h34.45 r45
  text "A5" at 16462.84,3126.58 h34.45 r45
  text "B10" at 16858.55,3118.29 h34.45 r45
  text "C14*" at 15556.26,3114 h34.45 r45
  text "VDD" at 15442.16,3111.82 h34.45 r45
  text "GND" at 16954.55,3112.29 h34.45 r45
  text "NRST" at 15734.26,3088 h34.45 r45
  text "RESET" at 14433.54,3077.31 h45.94
  text "USER" at 14956.09,3076.31 h45.94
  text "21" at 16463.01,3052.72 h38.28
  text "31" at 16962.01,3051.72 h38.28
  text "11" at 15969.01,3050.72 h38.28
  text "1" at 15475.58,3047.88 h37.97
Bottom Silkscreen Layer:
  text "61" at 15556.74,5818.69 h38.28 r315
  text "59" at 15665.74,5818.69 h38.28 r315
  text "57" at 15766.74,5818.69 h38.28 r315
  text "55" at 15864.74,5818.69 h38.28 r315
  text "53" at 15965.74,5818.69 h38.28 r315
  text "51" at 16065.74,5818.69 h38.28 r315
  text "39" at 16666.74,5818.69 h38.28 r315
  text "37" at 16767.74,5818.69 h38.28 r315
  text "35" at 16866.74,5818.69 h38.28 r315
  text "33" at 16971.74,5818.69 h38.28 r315
  text "63" at 15457.74,5813.69 h38.28 r315
  text "49" at 16168.74,5813.69 h38.28 r315
  text "43" at 16468.74,5813.69 h38.28 r315
  text "47" at 16265.74,5811.69 h38.28 r315
  text "45" at 16363.74,5811.69 h38.28 r315
  text "41" at 16566.74,5811.69 h38.28 r315
  text "64" at 15469.74,5543.69 h38.28 r315
  text "62" at 15569.74,5543.69 h38.28 r315
  text "60" at 15669.74,5543.69 h38.28 r315
  text "58" at 15774.74,5543.69 h38.28 r315
  text "50" at 16176.74,5543.69 h38.28 r315
  text "34" at 16975.74,5543.69 h38.28 r315
  text "52" at 16076.74,5542.69 h38.28 r315
  text "44" at 16478.74,5542.69 h38.28 r315
  text "42" at 16575.74,5542.69 h38.28 r315
  text "38" at 16776.74,5542.69 h38.28 r315
  text "36" at 16878.74,5542.69 h38.28 r315
  text "48" at 16281.74,5541.69 h38.28 r315
  text "46" at 16379.74,5541.69 h38.28 r315
  text "40" at 16677.74,5541.69 h38.28 r315
  text "56" at 15876.74,5538.69 h38.28 r315
  text "54" at 15976.74,5538.69 h38.28 r315
  text "VDD" at 13667.79,4636.62 h34.45 r270
  text "AT32F405RCT7-7" at 16719.3,4049.85 h114.84
  text "GND" at 13654.79,3786.62 h34.45 r270
  text "2" at 15466.17,3434.85 h37.97 r315
  text "8" at 15764.17,3433.2 h37.97 r315
  text "4" at 15564.17,3431.2 h37.97 r315
  text "6" at 15660.17,3431.2 h37.97 r315
  text "10" at 15867.74,3422.69 h38.28 r315
  text "12" at 15969.74,3422.69 h38.28 r315
  text "16" at 16167.74,3422.69 h38.28 r315
  text "14" at 16065.74,3420.69 h38.28 r315
  text "18" at 16262.74,3420.69 h38.28 r315
  text "20" at 16364.74,3419.69 h38.28 r315
  text "22" at 16471.74,3419.69 h38.28 r315
  text "24" at 16572.74,3419.69 h38.28 r315
  text "26" at 16669.74,3418.69 h38.28 r315
  text "28" at 16777.74,3418.69 h38.28 r315
  text "32" at 16971.74,3415.69 h38.28 r315
  text "30" at 16874.74,3414.69 h38.28 r315
  text "1" at 15456.17,3166.85 h37.97 r315
  text "5" at 15654.17,3165.2 h37.97 r315
  text "9" at 15856.17,3165.2 h37.97 r315
  text "3" at 15545.44,3163.38 h37.97 r315
  text "7" at 15752.17,3163.2 h37.97 r315
  text "11" at 15955.74,3162.69 h38.28 r315
  text "19" at 16367.74,3159.69 h38.28 r315
  text "15" at 16167.74,3158.69 h38.28 r315
  text "13" at 16066.74,3157.69 h38.28 r315
  text "21" at 16469.74,3157.69 h38.28 r315
  text "31" at 16971.74,3155.58 h38.28 r315
  text "17" at 16269.74,3154.69 h38.28 r315
  text "29" at 16884.74,3150.69 h38.28 r315
  text "25" at 16681.74,3147.69 h38.28 r315
  text "23" at 16580.74,3146.69 h38.28 r315
  text "27" at 16777.74,3144.69 h38.28 r315
Mechanical Layer:
  circle w1 net "": c17792.21,5902.56 r62.99
  circle w1 net "": c17791.58,3127.57 r62.99
  circle w1 net "": c14044.58,3127.57 r62.99
  circle w1 net "": c14044.58,5902.56 r62.99
  circle w1 net "": c17083.58,4865.56 r62.99
  circle w1 net "": c15033.58,3565.57 r62.99
  circle w1 net "": c15083.58,5465.56 r62.99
